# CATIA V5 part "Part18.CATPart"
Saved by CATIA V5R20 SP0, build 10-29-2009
Part number: 9TS1606M6
Revision: ANY
Definition: UNKNOWN
Nomenclature: 9TS1606M6
Source: Unknown
Bounding box of the stored display mesh (mm): x -8 to 8, y -8 to 8, z 0 to 6
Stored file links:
  C:\Users\Utente\Desktop\IO LAVORO\3D X SITO CF\CUMSA\3D files GR\GR 283432-10\Part18.CATPart
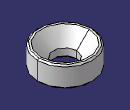
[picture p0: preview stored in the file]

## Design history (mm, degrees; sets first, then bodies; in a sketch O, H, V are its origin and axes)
Body1 "Chaflán1" (main body)
  Solid1: solid without history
